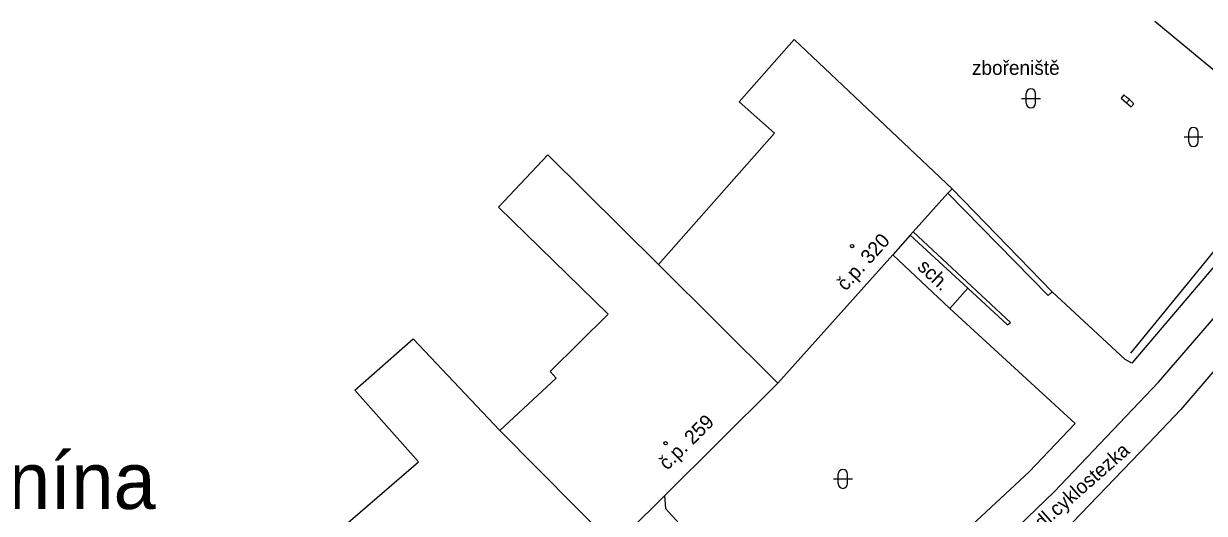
# Model space of a CAD drawing. Extents: x -577457 to -568404, y -1208466 to -1201387.
# Drawn here: x -569155.1 to -569092.8, y -1204594.6 to -1204568.7 of the extents above; entities that cross this region are included whole.
import ezdxf

# ---------------------------------------------------------------- set-up
doc = ezdxf.new("R2010")
doc.units = 0
for name, color, linetype in [('BUDOVY_MĚŘ', 7, 'Continuous'), ('BUDOVY_NEMĚŘ', 7, 'Continuous'), ('NÁZEV_K_Ú', 7, 'Continuous'), ('OBVOD_PILÍŘE', 7, 'Continuous'), ('POMOC_POPIS', 7, 'Continuous'), ('ROZHRANÍ_PLOCH', 7, 'Continuous'), ('ZN_BUDOV', 7, 'Continuous'), ('ZN_DOPLŇKOVÉ', 7, 'Continuous'), ('ZN_KULTUR', 7, 'Continuous'), ('Č_POPIS_ORIENT', 7, 'Continuous')]:
    doc.layers.add(name, color=color, linetype=linetype)

msp = doc.modelspace()

# ---------------------------------------------------------------- linework, layer by layer
at = {"layer": 'BUDOVY_MĚŘ'}
for points in [[(-569106.31, -1204577.69), (-569108.14, -1204579.74)], [(-569106.09, -1204577.46), (-569106.31, -1204577.69)], [(-569108.3, -1204579.92), (-569109.21, -1204580.95)], [(-569108.14, -1204579.74), (-569108.3, -1204579.92)], [(-569109.21, -1204580.95), (-569115.28, -1204587.72)], [(-569115.46, -1204587.9), (-569121.27, -1204593.68)], [(-569115.28, -1204587.72), (-569115.46, -1204587.9)]]:
    msp.add_lwpolyline(points, dxfattribs=at)
at = {"layer": 'BUDOVY_NEMĚŘ'}
for points in [[(-569106.09, -1204577.46), (-569114.42, -1204569.58), (-569117.33, -1204572.88), (-569115.46, -1204574.53), (-569121.59, -1204581.47)], [(-569121.59, -1204581.47), (-569127.42, -1204575.68), (-569130.02, -1204578.43), (-569124.24, -1204584.09), (-569127.3, -1204587.11), (-569126.99, -1204587.47), (-569129.95, -1204590.23)], [(-569121.59, -1204581.47), (-569115.28, -1204587.72)], [(-569140.92, -1204597.64), (-569134.25, -1204591.88), (-569137.61, -1204588.1), (-569134.53, -1204585.39), (-569129.95, -1204590.23)], [(-569129.95, -1204590.23), (-569123.92, -1204596.32)]]:
    msp.add_lwpolyline(points, dxfattribs=at)
at = {"layer": 'OBVOD_PILÍŘE'}
for points in [[(-569096.87, -1204572.64), (-569097.02, -1204572.51), (-569097.17, -1204572.68), (-569096.88, -1204572.93), (-569096.73, -1204572.76), (-569096.87, -1204572.64)], [(-569096.61, -1204572.87), (-569096.73, -1204572.76), (-569096.88, -1204572.93), (-569096.64, -1204573.14), (-569096.49, -1204572.98), (-569096.61, -1204572.87)]]:
    msp.add_lwpolyline(points, dxfattribs=at)
at = {"layer": 'ROZHRANÍ_PLOCH'}
for points in [[(-569193.54, -1204654.14), (-569180.57, -1204647.46), (-569168.09, -1204641.22), (-569155.65, -1204634.81), (-569151.19, -1204632.37), (-569146.32, -1204629.48), (-569140.18, -1204625.55), (-569133.63, -1204621.26), (-569127.76, -1204617.05), (-569123.45, -1204613.78), (-569117.55, -1204608.82), (-569108.26, -1204600.74), (-569100.71, -1204593.46), (-569095.2, -1204587.67), (-569088.24, -1204579.64), (-569082.76, -1204572.74), (-569075.37, -1204562.81), (-569068.38, -1204552.55), (-569060.81, -1204541.45), (-569052.52, -1204528.77), (-569045.02, -1204517.63), (-569041.38, -1204511.96), (-569040.25, -1204510.21)], [(-569095.39, -1204568.62), (-569090.4, -1204572.75), (-569089.94, -1204572.78), (-569087.13, -1204575.33)], [(-569087.13, -1204575.33), (-569087.86, -1204576.53), (-569088.79, -1204575.85), (-569090.44, -1204577.95), (-569089.71, -1204578.56), (-569096.6, -1204586.67), (-569096.95, -1204586.48), (-569100.8, -1204582.9)], [(-569106.2, -1204583.79), (-569099.6, -1204589.86), (-569102.02, -1204592.41), (-569109.57, -1204599.43), (-569113.42, -1204602.89)], [(-569090.51, -1204585.03), (-569094.01, -1204589.11), (-569095.72, -1204590.91), (-569099.74, -1204595.09), (-569101.17, -1204596.57), (-569104.45, -1204599.61), (-569107.01, -1204601.99), (-569112.62, -1204606.89), (-569116.49, -1204610.24), (-569121.4, -1204614.33), (-569122.18, -1204614.98), (-569126.64, -1204618.46), (-569129.19, -1204620.27), (-569132.62, -1204622.59), (-569135.85, -1204624.9), (-569139.4, -1204627.15), (-569142.68, -1204629.27), (-569145.19, -1204630.87), (-569150.36, -1204633.85), (-569154.83, -1204636.27), (-569162.74, -1204640.46), (-569167.51, -1204642.87), (-569179.77, -1204649.11), (-569191.34, -1204654.79)], [(-569121.27, -1204593.68), (-569121.22, -1204594.35), (-569113.42, -1204602.89)]]:
    msp.add_lwpolyline(points, dxfattribs=at)
at = {"layer": 'ZN_BUDOV'}
for centre in [(-569111.37, -1204580.49), (-569121.21, -1204590.9)]:
    msp.add_circle(centre, 0.0875, dxfattribs=at)
at = {"layer": 'ZN_DOPLŇKOVÉ'}
for points in [[(-569100.8, -1204582.9), (-569101.02, -1204583.1), (-569106.31, -1204577.69)], [(-569106.09, -1204577.46), (-569100.8, -1204582.9)], [(-569091.57, -1204577.62), (-569090.47, -1204578.54), (-569096.67, -1204586.14)], [(-569108.3, -1204579.92), (-569105.26, -1204582.71)], [(-569105.26, -1204582.71), (-569103.17, -1204584.65), (-569103.01, -1204584.52), (-569108.14, -1204579.74)], [(-569106.2, -1204583.79), (-569109.21, -1204580.95)], [(-569105.26, -1204582.71), (-569106.2, -1204583.79)], [(-569123.13, -1204595.53), (-569121.27, -1204593.68)]]:
    msp.add_lwpolyline(points, dxfattribs=at)
at = {"layer": 'ZN_KULTUR'}
for p, q in [((-569102.43, -1204572.69), (-569101.43, -1204572.69)), ((-569102.18, -1204572.94), (-569102.18, -1204572.44)), ((-569101.68, -1204572.94), (-569101.68, -1204572.44)), ((-569093.6, -1204574.98), (-569093.6, -1204574.48)), ((-569093.1, -1204574.98), (-569093.1, -1204574.48)), ((-569093.85, -1204574.73), (-569092.85, -1204574.73)), ((-569112.1, -1204593.03), (-569112.1, -1204592.53)), ((-569111.6, -1204593.03), (-569111.6, -1204592.53)), ((-569112.35, -1204592.78), (-569111.35, -1204592.78))]:
    msp.add_line(p, q, dxfattribs=at)
for centre, start, end in [((-569101.93, -1204572.44), 0, 179.99999), ((-569101.93, -1204572.94), 179.99999, 359.99999), ((-569093.35, -1204574.48), 0, 179.99999), ((-569093.35, -1204574.98), 179.99999, 359.99999), ((-569111.85, -1204592.53), 0, 179.99999), ((-569111.85, -1204593.03), 179.99999, 359.99999)]:
    msp.add_arc(centre, 0.25, start, end, dxfattribs=at)

# ---------------------------------------------------------------- texts
at = {"layer": 'NÁZEV_K_Ú'}
msp.add_text('k.ú.Lužice u Hodonína', height=3, dxfattribs=at).set_placement((-569188.03, -1204594.37))
at = {"layer": 'POMOC_POPIS'}
msp.add_text('zbořeniště', height=0.75, dxfattribs=at).set_placement((-569105.04, -1204571.45))
for s, rotation, p in [('sch.', 316.66455, (-569107.97, -1204581.65)), ('zám.dl.cyklostezka', 41.28, (-569102.98, -1204596.93))]:
    msp.add_text(s, height=0.75, rotation=rotation, dxfattribs=at).set_placement(p)
at = {"layer": 'Č_POPIS_ORIENT'}
for s, rotation, p in [('č.p. 320', 48.15, (-569111.7, -1204582.9)), ('č.p. 259', 44.86999, (-569121.12, -1204592.36))]:
    msp.add_text(s, height=0.75, rotation=rotation, dxfattribs=at).set_placement(p)

doc.saveas('drawing.dxf')
